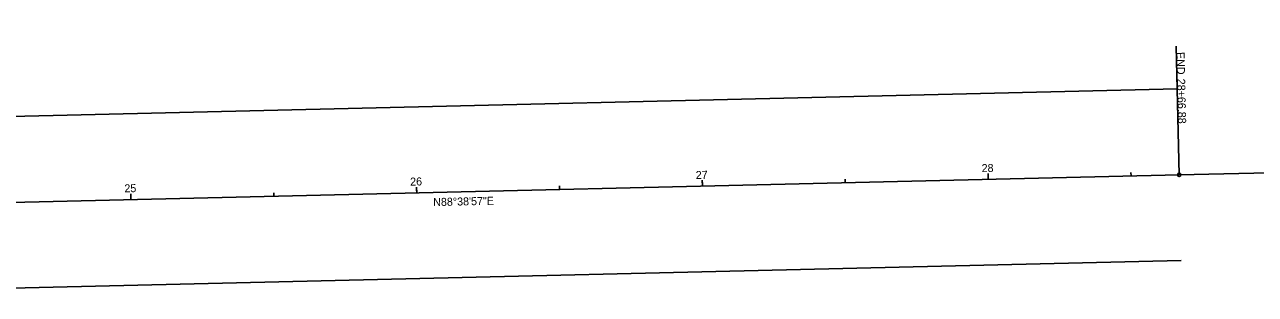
# Model space of a CAD drawing. Extents: x 2273856 to 2278684, y 652916 to 655179.
# Drawn here: x 2274968 to 2275398.6, y 654667.4 to 654761.7 of the extents above; entities that cross this region are included whole.
import ezdxf

# ---------------------------------------------------------------- set-up
doc = ezdxf.new("R2010")
doc.units = 0
for name, color, linetype in [('DV_X_Property_Line', 7, 'Continuous'), ('RW_X_CL', 7, 'Continuous'), ('RW_X_CL_1000_Curve_Data', 7, 'Continuous'), ('RW_X_CL_1000_Stations', 7, 'Continuous'), ('RW_X_CL_100_Curve_Data', 7, 'Continuous'), ('RW_X_CL_100_Stations', 7, 'Continuous'), ('RW_X_CL_500_Stations', 7, 'Continuous'), ('RW_X_Esmt_SH', 7, 'Continuous')]:
    doc.layers.add(name, color=color, linetype=linetype)

msp = doc.modelspace()

# ---------------------------------------------------------------- linework, layer by layer
at = {"layer": 'DV_X_Property_Line'}
msp.add_line((2275371.97, 654709.22), (2277597.03, 654761.7), dxfattribs=at)
at = {"layer": 'RW_X_CL'}
msp.add_line((2274872.11, 654697.43), (2275371.97, 654709.22), dxfattribs=at)
at = {"layer": 'RW_X_CL_1000_Stations'}
for p, q in [((2275371.97, 654709.22), (2275370.91, 654754.21)), ((2275005.19, 654700.57), (2275005.16, 654701.77))]:
    msp.add_line(p, q, dxfattribs=at)
msp.add_circle((2275371.97, 654709.22), 0.6, dxfattribs=at)
at = {"layer": 'RW_X_CL_100_Stations'}
for p, q in [((2275371.97, 654709.22), (2275370.91, 654754.21)), ((2275305.11, 654707.65), (2275305.06, 654709.65)), ((2275355.1, 654708.82), (2275355.07, 654710.02)), ((2275105.17, 654702.93), (2275105.12, 654704.93)), ((2275155.15, 654704.11), (2275155.12, 654705.31)), ((2275205.14, 654705.29), (2275205.09, 654707.29)), ((2275255.12, 654706.47), (2275255.1, 654707.67)), ((2275005.19, 654700.57), (2275005.15, 654702.57)), ((2275055.18, 654701.75), (2275055.15, 654702.95))]:
    msp.add_line(p, q, dxfattribs=at)
msp.add_circle((2275371.97, 654709.22), 0.6, dxfattribs=at)
at = {"layer": 'RW_X_CL_500_Stations'}
for p, q in [((2275371.97, 654709.22), (2275370.91, 654754.21)), ((2275305.11, 654707.65), (2275305.08, 654708.85)), ((2275105.17, 654702.93), (2275105.14, 654704.13)), ((2275205.14, 654705.29), (2275205.11, 654706.49)), ((2275005.19, 654700.57), (2275005.15, 654702.57))]:
    msp.add_line(p, q, dxfattribs=at)
msp.add_circle((2275371.97, 654709.22), 0.6, dxfattribs=at)
at = {"layer": 'RW_X_Esmt_SH'}
for p, q in [((2274871.4, 654727.43), (2275371.26, 654739.21)), ((2274872.82, 654667.44), (2275372.68, 654679.23))]:
    msp.add_line(p, q, dxfattribs=at)

# ---------------------------------------------------------------- texts
at = {"layer": 'RW_X_CL_1000_Curve_Data'}
msp.add_text('N88°38\'57"E', height=2.8, rotation=1.351, dxfattribs=at).set_placement((2275110.98, 654698.27))
at = {"layer": 'RW_X_CL_1000_Stations'}
for s, p in [('END', (2275371.01, 654752.11)), ('28+66.88', (2275371.23, 654742.77))]:
    msp.add_text(s, height=2.8, rotation=271.351, dxfattribs=at).set_placement(p)
at = {"layer": 'RW_X_CL_100_Curve_Data'}
msp.add_text('N88°38\'57"E', height=2.8, rotation=1.351, dxfattribs=at).set_placement((2275110.98, 654698.27))
msp.add_text('N88°38\'57"E', height=2.8, rotation=1.351, dxfattribs=at).set_placement((2275110.98, 654698.27))
at = {"layer": 'RW_X_CL_100_Stations'}
for s, rotation, p in [('END', 271.351, (2275371.01, 654752.11)), ('28+66.88', 271.351, (2275371.23, 654742.77)), ('28', 1.351, (2275302.86, 654710.14)), ('26', 1.351, (2275102.91, 654705.43)), ('27', 1.351, (2275202.83, 654707.73)), ('25', 1.351, (2275002.93, 654703.07))]:
    msp.add_text(s, height=2.8, rotation=rotation, dxfattribs=at).set_placement(p)
at = {"layer": 'RW_X_CL_500_Stations'}
for s, rotation, p in [('END', 271.351, (2275371.01, 654752.11)), ('28+66.88', 271.351, (2275371.23, 654742.77)), ('25', 1.351, (2275002.93, 654703.07))]:
    msp.add_text(s, height=2.8, rotation=rotation, dxfattribs=at).set_placement(p)

doc.saveas('drawing.dxf')
